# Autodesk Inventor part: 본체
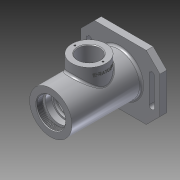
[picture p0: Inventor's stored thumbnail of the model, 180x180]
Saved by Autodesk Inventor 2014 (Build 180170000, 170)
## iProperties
Created: 2017-10
Part Number: 본체
Material: 알루미늄 6061
Document SubType Name: Modeling
Designer: net
Mass: 738.275 g
Surface Area: 652.722 cm^2
Volume: 272.426 cm^3
Density: 2.71 g/cm^3
Appearance: 알루미늄 - 평지
Author: net
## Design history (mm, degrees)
sketch "스케치1"
  geometry: L1 (0, 0)-(-115, 0); L2 (-115, 0)-(-115, 31); L3 (-115, 31)-(-13, 31); L4 (-13, 31)-(-13, 31); L5 (-13, 31)-(-3, 31); L6 (-3, 31)-(-3, 35); L7 (-3, 35)-(0, 35); L8 (0, 35)-(0, 0); L9 (-115, 21)-(-106, 21); L10 (-106, 21)-(-106, 24); L11 (-106, 24)-(-103, 24); L12 (-103, 24)-(-103, 20); L13 (-103, 20)-(-94, 20); L14 (-94, 20)-(-94, 17.5); L15 (-94, 17.5)-(-90.75, 17.5); L16 (-90.75, 17.5)-(-90.75, 18.5); L17 (-90.75, 18.5)-(-89, 18.5); L18 (-89, 18.5)-(-89, 17.5); L19 (-89, 17.5)-(-78, 17.5); L20 (-78, 17.5)-(-78, 26); L21 (-78, 26)-(-40, 26); L22 (-40, 26)-(-40, 17.5); L23 (-40, 17.5)-(-29, 17.5); L24 (0, 22)-(-14, 16); L25 (-29, 17.5)-(-29, 16.5); L26 (-29, 16.5)-(-24, 16.5); L27 (-24, 16.5)-(-24, 10); L28 (-24, 10)-(-21.3, 10); L29 (-21.3, 10)-(-21.3, 12.5); L30 (-21.3, 12.5)-(-14.7, 12.5); L31 (-14.7, 12.5)-(-14, 12.904); L32 (-14, 12.904)-(-14, 16); 1 further point
  constraints: 64 end point, 16 perpendicular, 10 parallel, 3 horizontal, 2 point on line, 1 coincident, 1 vertical
  dimensions: "d0" = 115 distance of L1.start L1.end; "d1" = 3 distance of L6.end L7.end; "d2" = 13 distance between parallel lines of L4 L8; "d3" = 70 diameter of L7 L1; "d4" = 62 diameter of L3 L1; "d5" = 62 diameter of L5 L1; "d6" = 42 diameter of L9 L1; "d7" = 48 diameter of L11 L1; "d8" = 40 diameter of L13 L1; "d9" = 35 diameter of L15 L1; "d10" = 3 distance of L10.end L11.end; "d11" = 12 distance between parallel lines of L2 L12; "d12" = 21 distance between parallel lines of L2 L14; "d14" = 1.75 distance of L16.end L17.end; "d15" = 37 diameter of L17 L1; "d16" = 26 distance between parallel lines of L2 L18; "d17" = 11 distance of L18.end L19.end; "d18" = 35 diameter of L19 L1; "d19" = 38 distance of L20.end L21.end; "d20" = 52 diameter of L21 L1; "d21" = 11 distance of L22.end L23.end; "d22" = 35 diameter of L23 L1; "d23" = 44 diameter of L24.start L1; "d24" = 32 diameter of L24.end L1; "d25" = 14 horizontal distance of L24.start L24.end; "d26" = 5 distance of L25.end L26.end; "d27" = 33 diameter of L26 L1; "d28" = 2.7 distance of L27.end L28.end; "d29" = 20 diameter of L28 L1; "d30" = 0.7 horizontal distance of L31.end L30.end; "d31" = 30 deg angle of L30 L31; "d32" = 25 diameter of L30 L1
revolve "회전1" sketch "스케치1" stored, may be unused: angle "d33" = 90 deg
fillet "모깎기1" dims "d34" = 0.3
fillet "모깎기2" dims "d35" = 0.3
fillet "모깎기3" dims "d36" = 3
fillet "모깎기4" dims "d37" = 3
feature "스레드1" dims "d38" = 10, "d39" = 0
node "작업 평면1"
sketch "스케치3"
  geometry: L1 (-115, -31)-(-115, 31) reference; C1 r 25 at (-59, 0); 1 further point
  constraints: 1 centre point, 1 horizontal alignment
  dimensions: "d41" = 50 diameter of C1; "d42" = 56 distance from line of C1.centre L1
extrude "돌출1" join sketch "스케치3" stored distance "d43" = 10; taper "d44" = 0 deg
sketch "스케치4"
  geometry: C1 r 25 at (0, 0) reference; C2 r 16 at (0, 0); 1 further point
  constraints: 1 centre point, 1 coincident
  dimensions: "d45" = 32 diameter of C2
extrude "돌출2" cut sketch "스케치4" stored distance "d46" = 10; taper "d47" = 0 deg
sketch "스케치5" dims "d48" = 41
  geometry: C1 r 25 at (0, 0) reference; 3 further points
  constraints: 2 vertical alignment, 1 coincident, 2 other
hole "구멍1" sketch "스케치5" at (0, 20.5) diameter "d49" = 2.459; stored, may be unused: countersink angle "d53" = 90 deg, drill point angle "d55" = 118 deg; dims "d50" = 6, "d51" = 4, "d52" = 2, "d54" = 8
node "작업 평면2"
sketch "스케치6"
  geometry: L1 (47, -58)-(-47, -58); L2 (-47, -58)-(-47, 58); L3 (-47, 58)-(47, 58); L4 (47, 58)-(47, -58); L5 (47, -58)-(-47, 58); L6 (-47, -58)-(47, 58); C1 r 31 at (0, 0) reference; C2 r 16.429 at (0, 0) reference; 1 further point
  constraints: 12 end point, 2 midpoint, 2 parallel, 1 horizontal, 1 perpendicular
  dimensions: "d60" = 94 distance of L2.end L3.end; "d61" = 116 distance of L1.end L2.end
extrude "돌출3" join sketch "스케치6" distance "d62" = 10; taper "d63" = 0 deg
sketch "스케치7"
  geometry: L1 (-47, -58)-(47, -58) reference; L2 (47, -58)-(47, 58) reference; L3 (-47, 58)-(-47, -58) reference; L4 (-20, 46)-(20, 46); L5 (-20, 42)-(20, 42); L6 (20, 50)-(-20, 50); L7 (-47, 0)-(47, 0); L8 (-20, -42)-(20, -42); L9 (20, -50)-(-20, -50); C1 r 35 at (0, 0) reference; A1 r 4 centre (-20, 46) between (-20, 50) and (-20, 42); A2 r 4 centre (20, 46) between (20, 42) and (20, 50); A3 r 4 centre (-20, -46) between (-20, -42) and (-20, -50); A4 r 4 centre (20, -46) between (20, -50) and (20, -42); 1 further point
  constraints: 14 end point, 8 point on circle, 6 symmetric about line, 4 centre point, 4 tangent, 3 midpoint, 2 parallel, 1 vertical alignment, 2 other
  dimensions: "d64" = 40 distance of L4.start L4.end; "d65" = 46 distance from line of C1.centre L4; "d66" = 4 radius of A1
extrude "돌출4" cut sketch "스케치7" stored distance "d67" = 10; taper "d68" = 0 deg
chamfer "모따기1" distance "d69" = 20; stored, may be unused: second distance "d70" = 2, angle "d71" = 45 deg
fillet "모깎기5" dims "d72" = 3
chamfer "모따기2" distance "d73" = 1; stored, may be unused: second distance "d74" = 2, angle "d75" = 45 deg
chamfer "모따기3" distance "d76" = 1; stored, may be unused: second distance "d77" = 2, angle "d78" = 45 deg
node "작업 평면3"
sketch "스케치9"
  geometry: L1 (-115, -31)-(-115, 31) reference; L2 (-84, 47)-(-34, 47) reference; 2 further points
  constraints: 1 other
  dimensions: "d80" = 56 distance from line of L1 point (-59, 37); "d81" = 10 distance from line of point (-59, 37) L2
feature "엠보싱1" sketch "스케치9" dims "d16" = 26, "d82" = 0.5, "d83" = 0
node "솔리드1"
pattern_circular "원형 패턴1" dims angle "d57" = 360 deg
node "절단 모서리 투영1"
other parameters: "d40" = 47, "d59" = -13, "d79" = -25
